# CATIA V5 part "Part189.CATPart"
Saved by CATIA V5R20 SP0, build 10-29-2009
Part number: IA 8717SF
Revision: ANY
Definition: UNKNOWN
Nomenclature: IA 8717SF
Source: Unknown
Bounding box of the stored display mesh (mm): x -4.35 to 4.35, y -17 to 0, z -4.35 to 4.35
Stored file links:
  C:\Users\Utente\Desktop\IO LAVORO\3D X SITO CF\CUMSA\3D files FA\FA 168700\Part189.CATPart
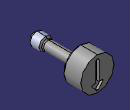
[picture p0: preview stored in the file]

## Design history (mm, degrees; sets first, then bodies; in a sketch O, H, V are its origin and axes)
Body1 "Cortar-Extruir1" (main body)
  Solid1: solid without history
